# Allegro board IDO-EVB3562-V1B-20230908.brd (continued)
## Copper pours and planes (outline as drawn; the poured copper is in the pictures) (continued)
VCC_3V3 on TOP: 13.57,13.88 12.76,13.88 12.56,13.67 12.56,13.19 12.33,12.96 11.64,12.96 11.58,13.03 11.58,14.1 11.59,14.1 11.82,14.33 11.97,14.33 12.18,14.54 12.18,14.99 14,16.8 14.18,16.8 14.43,16.55 14.43,15.39 13.72,14.68 13.72,14.03
VCC_3V3 on TOP: 27.95,13.93 27.85,14.03 27.85,15.37 28.02,15.55 30.13,15.55 30.28,15.4 30.28,14.31 29.9,13.93
VCC_3V3 on BOTTOM: 7.07,64.04 6.84,64.27 6.84,65.64 7.02,65.82 7.78,65.82 8.13,66.17 8.18,66.17 8.18,66.22 9.99,68.03 26.58,68.03 27.13,68.59 27.13,69.63 27.62,70.11 28.15,70.11 28.16,70.1 28.65,70.1 28.66,70.09 29.55,70.09 30.26,69.37 30.26,66.53 29.22,65.49 9.89,65.49 9.56,65.16 9.56,65.14 8.46,64.04
VCC_3V3 on BOTTOM: outline of 202 points within 6.13,7.27 74.61,39.02
VCC_3V3 on L2-VCC: 78.11,71.94 78.11,70.52 76.94,69.35 72.4,69.35 69.98,66.94 65.41,66.94 63.18,69.17 59.32,69.17 58.25,68.1 58.25,66.07 58.96,65.36 58.96,64.96 58.81,64.8 58.25,64.8 58.1,64.96 30.06,64.96 27.24,67.77 27.24,69.91 27.87,70.54 34.68,70.54 38.36,66.86 53.37,66.86 57.21,70.7 64.24,70.7 66.2,68.74 68.79,68.74 71.33,71.28 76.11,71.28 76.84,72.02 78.04,72.02
VCC_3V3 on L2-VCC: 3.46,63.15 3.46,42.83 5.11,41.18 5.11,35.59 5.49,35.21 8.03,35.21 8.54,35.72 8.54,42.2 8.48,42.26 8.48,52.67 6.26,54.9 6.26,62.39 6.64,62.77 9.05,62.77 9.43,63.15 9.43,66.2 9.11,66.52 6.45,66.52 5.75,65.82 5.75,64.8 5.24,64.29 4.6,64.29
VCC_DCIN on TOP: 10.14,76.46 10.14,74.07 14.33,74.07 14.33,76.28 12.52,78.1 11.78,78.1
VCC_DCIN on L2-VCC: 14.31,75.42 14.31,73.87 13.75,73.31 12.33,73.31 10.85,71.84 10.85,69.81 9.43,68.38 5.87,68.38 4.73,67.24 4.73,64.8 3.08,63.15 3.08,42.58 4.73,40.93 4.73,35.47 5.37,34.83 7.53,34.83 7.78,34.58 7.78,27.59 7.4,27.21 4.94,27.21 4.22,26.5 1.76,26.5 1.23,27.03 1.23,69.12 3.08,70.98 6.69,70.98 8.95,73.24 8.95,76.46 6.76,78.65 1.91,78.65 1.37,79.19 1.37,83.71 2.67,85.02 9.35,85.02 10.32,84.06 10.32,79.41
VCC_DMIC on TOP: 64.88,7.14 63.15,5.42 62.52,5.42 62.42,5.52 62.42,7.93 62.77,8.29 72.42,8.29 72.55,8.16 72.55,7.53 72.17,7.14
VCC_LEDA+ on TOP: 2.93,67.21 5.91,67.21 5.91,67.22 7.12,67.22 7.27,67.06 7.27,66.05 7.25,66.02 4.73,66.02 4.38,66.02 4.1,65.74 4.1,63.58 5.24,62.44 5.24,58.99 4.91,58.66 3.18,58.66 2.57,59.27 2.57,66.86
VCC_LEDA+ on BOTTOM: 4.16,56.93 2.83,56.93 2.57,57.18 2.57,59.21 2.68,59.32 3.37,59.32 3.37,59.34 3.59,59.34 3.72,59.47 3.72,61.75 3.84,61.88 4.6,61.88 5.58,60.9 5.58,58.35
VCC_LEDA+ on BOTTOM: 3.82,66 3.69,66.12 3.69,67.17 3.79,67.27 5.39,67.27 5.52,67.14 5.52,66.1 5.42,66 5.25,66 5.24,66 5.09,66.02 4.95,66 4.94,66
VCC_LEDK- on TOP: 5.72,65.77 5.72,65.76 7.2,65.76 7.27,65.69 7.27,65.03 7.21,64.97 5.72,64.97 5.72,64.96 5.57,64.96 5.19,64.57 4.63,64.57 4.4,64.8 4.4,65.44 4.73,65.77
VCC_LEDK- on BOTTOM: 3.82,64.78 3.82,65.64 3.92,65.74 6.48,65.74 6.56,65.67 6.56,64.85 6.33,64.63 3.97,64.63
VCC_M2 on TOP: 96.76,28.89 96.76,28.05 96.73,28.02 96.29,28.02 96.29,28.03 96.04,28.06 95.8,28.03 95.77,28.02 95.69,27.99 95.65,27.97 95.58,27.94 95.52,27.9 94.39,27.9 94.14,28.15 94.14,30.18 94.44,30.49 94.44,32.09 94.5,32.14 96.3,32.14 96.55,31.88 96.55,29.09
VCC_M2 on TOP: 99.47,42.58 98.97,42.07 98.97,38.33 98.17,37.53 96.27,37.53 96.17,37.62 96.17,38.49 96.4,38.89 96.17,39.3 96.17,39.51 96.4,39.91 96.17,40.32 96.17,40.52 96.4,40.93 96.17,41.33 96.17,43.47 96.04,43.59 96.04,44.74 95.95,44.83 95.77,45.03 95.51,45.1 95.38,45.22 95.38,45.83 95.56,46.01 95.64,46.01 95.84,45.95 96.04,45.94 96.24,45.95 96.44,46 96.45,46.01 96.55,46.01 96.65,46.1 96.77,46.19 96.89,46.29 96.98,46.4 97.06,46.51 99.35,46.51 99.47,46.39 99.47,44.74
VCC_M2 on BOTTOM: 95.68,38.48 96.1,38.45 96.38,38.77 98.02,38.77 98.71,38.07 98.71,34.35 98.69,34.33 98.69,30.43 98.71,30.41 98.71,28.18 98.38,27.85 96.64,27.85 95.95,28.05 95.32,27.72 93.88,27.72 93.25,28.34 93.25,28.61 93.41,28.76 95.32,28.76 95.32,29.03 95.41,29.12 95.41,30.39 95.32,30.39 95.32,30.47 93.42,30.47 93.38,30.51 93.38,30.63 93.38,30.64 93.44,30.87 93.38,31.1 93.38,31.11 93.38,31.31 93.38,31.32 93.44,31.55 93.38,31.79 93.38,32.16 93.48,32.26 95.32,32.26 95.32,32.29 95.41,32.29 95.41,38.26 95.65,38.5
VCC_M2 on BOTTOM: 93.7,44.99 93.62,45.02 93.59,45.1 93.6,45.14 93.6,46.39 95.03,46.39 95.28,46.13 95.39,46.13 95.4,46.13 96.04,45.94 96.69,46.13 96.7,46.13 97.06,46.13 97.29,45.91 97.29,44.71 97.19,44.61 96.17,44.61 95.95,44.83 95.62,45.08 95.22,44.99
VCC_OUT on TOP: 124.37,5.85 124.37,3.06 124.26,2.95 123.12,2.95 123.11,2.96 122.84,2.99 122.57,2.96 122.56,2.95 122.2,2.95 121.78,3.37 121.74,3.37 121.6,3.51 121.6,5.62 121.27,5.95 121.27,7.83 121.34,7.91 122.36,8.19 123.5,8.19 123.78,7.91 124.8,7.91 124.87,7.83 124.87,6.36
VCC_OUT on TOP: 86.27,7.02 90.61,7.02 90.94,6.69 90.94,2.37 90.76,2.19 88.93,2.19 87.28,3.84 81.69,3.84 80.72,2.87 80.72,2.15 80.47,1.91 79.64,1.91 79.29,2.26 79.29,3.25 81.41,5.37 82.71,5.37 83.24,5.9 85.15,5.9
VCC_OUT on BOTTOM: outline of 82 points within 87.05,1.28 124.75,6.76
VCC_RMII on BOTTOM: 40.27,60.9 40.11,60.9 39.64,60.43 39.2,60.43 39.17,60.46 39.17,61.04 39.53,61.4 39.53,64.45 39.76,64.68 41.28,64.68 41.49,64.47 41.49,64.19 41.84,63.84 41.84,61.4 41.7,61.26 40.53,61.26 40.42,61.15 40.42,61.06
VCC_SIM on TOP: 109.25,59.47 109.25,60.28 109.51,60.54 114.76,60.54 115.4,59.9 117.13,59.9 117.43,59.6 117.43,58.81 117.38,58.76 114.89,58.76 114.36,59.29 109.43,59.29
VCC_SIM on BOTTOM: 108.24,58.99 107.95,59.27 107.89,59.35 107.81,59.42 106.69,60.54 106.69,62.31 106.94,62.57 108.24,62.57 108.41,62.39 108.41,60.64 108.74,60.31 110.42,60.31 110.83,59.9 110.83,59.09 110.73,58.99
VCC_SIM on BOTTOM: 115.22,57.46 114.79,57.89 114.79,58.99 114.87,59.06 115.83,59.06 116.14,59.37 117.25,59.37 117.58,59.04 117.58,57.61 117.43,57.46
VCC_SYS on TOP: 26.38,56.09 26.17,56.29 25.58,56.29 25.48,56.19 24.81,56.19 24.81,56.99 24.75,56.99 24.75,57.03 23.65,58.12 23.65,67.47 23.83,67.65 27.85,67.65 28.35,67.14 28.35,65.92 29.12,65.16 30.39,65.16 30.84,64.7 30.84,60.94 30.84,60.94 30.8,60.74 30.84,60.54 30.84,60.53 30.84,58.88 30.23,58.28 30.23,56.32 30.13,56.22 27.08,56.22 26.98,56.12 26.62,56.12 26.6,56.09
VCC_TP on TOP: 10.83,34.7 11.67,35.54 13.02,35.54 13.11,35.45 13.1,35.42 13.09,35.32 13.11,35.22 13.11,35.21 13.11,34.09 13.29,33.92 13.29,33.05 13.23,32.99 12.28,32.99 12.26,33 12.25,33.02 12,33.19 11.7,33.18 11.69,33.18 10.93,33.18 10.83,33.28
VCCA_RMII on BOTTOM: 35.26,59.34 35.16,59.45 35.16,59.49 35.16,60.27 35.11,60.27 35.11,60.48 35.29,60.66 35.29,61.93 35.59,62.24 36.58,62.24 36.81,62.47 38.97,62.47 39.07,62.36 39.07,61.37 38.95,61.25 38.08,61.25 37.23,60.4 35.91,60.4 35.9,60.38 35.75,60.38 35.63,60.27 35.48,60.27 35.48,59.49 35.48,59.45 35.49,59.41 35.42,59.34
VCCIO_WL on TOP: 113.09,28.48 112.94,28.63 112.94,29.09 111.79,30.23 110.27,30.23 110.01,30.49 110.01,31.63 110.17,31.78 112.43,31.78 112.81,31.4 113.6,31.4 113.67,31.33 113.67,28.51 113.65,28.48
VDD10_PHY0 on BOTTOM: 47.63,52.46 47.63,52.79 47.73,52.89 48.37,52.89 48.42,52.84 48.42,50.71 48.29,50.58 47.66,50.58 47.4,50.33 47.4,49.69 47.28,49.56 46.77,49.56 46.57,49.77 46.57,50.1 46.55,50.11 46.55,50.15 45.92,50.78 45.92,51.63 46.13,51.85 47.02,51.85 47.27,52.1 47.28,52.1 47.49,52.22 47.61,52.43 47.61,52.44
VDD10_PHY2 on BOTTOM: 70.76,49.57 70.62,49.72 70.62,50.55 70.47,50.71 70.29,50.71 70.29,50.72 69.46,50.72 69.3,50.88 69.3,51.87 69.4,51.98 72.04,51.98 72.7,51.32 73.34,51.32 73.44,51.21 73.44,49.69 73.32,49.57
VDD_3V8 on TOP: 106.94,54.21 106.94,55.02 106.57,55.39 105.58,55.39 105.44,55.53 105.44,56.04 105.67,56.27 108.39,56.27 108.43,56.31 108.44,56.32 108.44,58.61 108.52,58.68 109.02,58.68 109.1,58.61 109.1,54.62 109.05,54.57 108.19,54.57 107.96,54.34 107.96,54.21 107.78,54.03 107.12,54.03
VDD_3V8 on TOP: 120.4,56.27 120.45,56.32 120.48,58.58 121.7,58.58 122.46,58.58 122.64,58.4 122.64,54.16 122.59,54.11 122.59,53.35 121.92,52.68 120.78,52.68 120.4,53.06
VDD_3V8 on TOP: 101.79,64.45 101.64,64.59 101.64,66.95 101.63,66.95 101.63,68.59 101.75,68.7 103.58,68.7 104.22,69.35 104.93,69.35 105.27,69.02 105.27,67.65 104.6,66.99 103.18,66.99 103.14,66.95 103.12,66.95 103.12,66.93 103.11,66.91 103.11,64.65 102.9,64.45
VDD_3V8 on TOP: 99.07,51.8 98.61,51.34 94.14,51.34 93.89,51.59 93.89,54.26 93.43,54.72 93.43,56.88 93.61,57.06 94.6,57.06 95.05,57.51 95.05,58.99 95.38,59.32 97.72,59.32 97.89,59.15 97.89,58.75 97.9,58.73 97.9,56.32 98.13,56.09 99.22,56.09 99.45,55.86 99.45,54.21 99.07,53.83
VDD_3V8 on BOTTOM: outline of 85 points within 96.55,48.93 123.05,68.08
VDD_5V on TOP: 14.26,49.44 14.29,49.47 14.46,49.82 14.45,50.22 14.38,50.41 14.26,50.58 14.26,51.24 14.31,51.29 15.58,51.29 15.78,51.09 17.3,51.09 17.89,50.51 17.89,50.5 17.98,50.37 18.11,50.28 18.12,50.27 19.79,48.6 19.79,43.82 20.12,43.49 20.12,42.12 19.82,41.82 18.83,41.82 18.45,42.2 18.45,44.51 18.49,44.51 18.49,45.47 18.41,45.55 18.02,45.55 17.85,45.71 17.85,47.8 16.95,48.7 14.99,48.7
VDD_5V on TOP: 83.92,11.78 81.33,11.78 81.19,11.92 81.19,13.11 80.8,13.49 79.53,13.49 79.41,13.62 79.41,14.51 79.79,14.89 81.57,14.89 83.47,12.99 83.98,12.99 84.11,12.86 84.11,11.97
VDD_5V on BOTTOM: outline of 177 points within 0.87,1.27 84.46,51.72 ; 1 cut-out
VDD_LCD on TOP: 9.43,38.01 9.56,38.13 9.56,38.77 9.68,38.89 10.32,38.89 10.45,38.77 11.84,38.77 11.97,38.89 11.97,41.23 12.12,41.38 13.34,41.38 13.65,41.08 13.65,36.79 10.37,36.79 8.77,35.19 8.77,29.4 8.62,29.24 5.85,29.24 5.14,29.95 5.14,37.57 5.57,38.01
VDD_LCD_ on TOP: 10.7,43.85 10.84,43.99 10.84,46.3 11.31,46.77 12.48,46.77 12.86,47.15 12.86,48.37 13.24,48.75 13.98,48.75 15.78,46.95 15.78,42.07 15.53,41.82 11.08,41.82 10.7,42.2
(no net) on TOP: 0.51,87.97 0.95,89.05 2.03,89.49 118.47,89.49 118.65,89.31 118.65,88.55 118.78,88.42 122.97,88.42 123.1,88.55 123.1,89.31 123.27,89.49 132.97,89.49 134.05,89.05 134.49,87.97 134.49,2.03 134.05,0.95 132.97,0.51 2.03,0.51 0.95,0.95 0.51,2.03 ; 117 cut-outs
(no net) on BOTTOM: 2.03,0.51 0.95,0.95 0.51,2.03 0.51,87.97 0.95,89.05 2.03,89.49 13.75,89.49 13.75,77.29 15.32,75.72 17.69,75.72 18.7,76.74 18.7,78.77 16.92,80.55 16.92,86.56 17.13,86.77 31.32,86.77 31.53,86.56 31.53,80.8 29.75,79.03 29.75,76.87 31.02,75.6 36.31,75.6 37.75,77.04 37.75,78.6 35.85,80.51 35.85,85.93 36.69,86.77 50.62,86.77 50.96,86.44 50.96,81.02 49.05,79.11 49.05,76.78 50.24,75.6 56.12,75.6 57.69,77.17 57.69,78.73 55.53,80.89 55.53,86.18 55.87,86.52 70.18,86.52 70.39,86.31 70.39,80.76 68.49,78.86 68.49,76.91 69.67,75.72 72.13,75.72 73.44,77.04 73.44,89.49 118.47,89.49 118.65,89.31 118.65,88.55 118.78,88.42 122.97,88.42 123.1,88.55 123.1,89.31 123.27,89.49 132.97,89.49 134.05,89.05 134.49,87.97 134.49,2.03 134.05,0.95 132.97,0.51 ; 97 cut-outs
HP_SNS on TOP (solid shape): 124.47,87.35 125.53,86.63 123.39,86.12 123.29,86.15 123.25,86.25 123.37,88.03
HPL_OUT+ on TOP (solid shape): 124.48,80.79 125.53,80.08 123.36,79.95 123.27,79.99 123.23,80.08 123.37,81.48
HUB_1V8 on BOTTOM: 119.18,40.29 118.4,40.29 117.63,41.05 117.63,45.75 116.11,47.28 109.51,47.28 109,46.77 109,45.24 107.73,43.97 106.79,43.97 106.48,44.28 106.48,44.69 107.16,45.36 107.16,48.79 107.68,49.31 112.43,49.31 113.32,48.42 116.26,48.42 118.96,45.73 118.96,41.53 118.96,41.51 119.46,41 119.46,40.58
HUB_3V3 on TOP: 117.76,50.58 117.76,49.77 116.21,48.22 116.21,47.38 116.06,47.23 115.6,47.23 115.53,47.3 115.53,47.4 115.53,47.44 115.53,48.81 115.53,48.85 115.53,49.46 116.7,50.63 117.71,50.63
HUB_3V3 on TOP: 111.34,40.42 111.34,38.74 111.54,38.54 111.84,38.54 112.05,38.74 112.05,40.39 112.12,40.47 112.28,40.47 112.35,40.39 112.35,40.29 112.34,40.26 112.34,38.89 112.35,38.85 112.35,38.82 112.35,37.37 112.22,37.24 110.42,37.24 110.4,37.27 110.4,38.13 110.85,38.59 110.93,38.64 110.99,38.72 111.03,38.77 111.03,40.42 111.11,40.5 111.26,40.5
HUB_3V3 on BOTTOM: 105.54,41.97 105.54,43.31 105.06,43.72 105.04,44.52 105.05,44.56 105.06,44.66 105.04,44.76 105.03,45.09 105.87,45.93 105.87,48.19 106.23,48.55 106.71,48.55 106.87,48.39 106.87,45.5 106.23,44.86 106.23,44.18 106.87,43.54 106.89,43.54 110.01,40.42 117.63,40.42 118.02,40.04 119.29,40.04 119.79,40.55 119.79,41.05 119.21,41.64 119.21,45.88 116.67,48.42 116.67,48.45 116.36,48.75 114.03,48.75 112.78,49.99 112.78,50.32 113.27,50.81 113.67,50.81 114.49,49.99 116.7,49.99 120.23,46.46 120.23,44.61 121.37,43.47 121.37,39.74 119.63,38.01 107.81,38.01 106.75,39.06 106.75,40.76
PA_5V on TOP: 86.08,15.21 88.68,15.21 89.24,15.77 89.83,15.77 89.85,15.78 91.75,15.78 91.83,15.86 99.85,15.86 100.13,15.58 100.13,14.61 100.03,14.51 98.71,14.51 98.6,14.4 95.91,14.4 95.91,14.36 92.12,14.36 92.12,14.4 89.81,14.4 89.81,14.37 89.69,14.26 89.69,13.62 89.57,13.49 86.29,13.49 86.28,13.51 85.76,12.99 85.76,11.97 85.63,11.84 84.74,11.84 84.61,11.97 84.61,13.75
PHY0_REG_OUT on BOTTOM: 49.77,50.81 49.69,50.88 49.69,53.53 49.95,53.78 49.98,53.78 49.98,53.82 51.37,55.2 52.56,55.2 52.69,55.08 52.68,54.96 52.68,54.56 52.64,54.52 52,54.52 50.58,53.09 50.58,51.35 50.51,51.28 50.46,51.2 50.41,51.07 50.41,50.92 50.38,50.84 50.31,50.81
PHY2_REG_OUT on BOTTOM: 69.43,53.25 69.32,53.35 69.32,53.73 69.43,53.85 69.49,54 69.49,54.25 69.38,54.47 69.38,54.48 69.36,54.52 69.56,54.73 70.33,54.73 71,55.4 71,56.42 71.34,56.76 71.41,56.75 71.97,56.75 72.08,56.77 72.18,56.83 72.39,56.83 72.39,56.73 72.39,55.52 72.11,55.24 71.83,55.11 71.69,54.83 71.66,54.8 71.66,53.47 71.43,53.25
SIM_CLK on BOTTOM (solid shape): 113.28,60.58 112.72,60.02 112.68,60.01 112.64,60.02 112.08,60.58 112.68,61.51
SIM_DATA on BOTTOM (solid shape): 113.31,83.75 112.72,83.17 112.68,83.15 112.64,83.17 112.06,83.75 112.68,84.68
SIM_RST on BOTTOM (solid shape): 110.85,62.48 110.9,62.46 110.91,62.41 110.84,60.58 110.13,61.49 109.44,62.41
USB_OTG on TOP: 97.06,74.71 95.79,73.44 95.79,70.26 94.52,70.26 94.52,75.22 95.16,75.85 95.16,77.5 95.41,77.76 96.81,77.76 97.06,77.5
USB_OTG on BOTTOM: 94.9,81.06 90.08,81.06 89.82,80.8 89.82,79.92 90.08,79.66 91.6,79.66 92.74,78.52 94.14,78.52 95.16,77.5 95.16,76.74 95.41,76.49 95.66,76.49 96.81,77.63 96.81,79.15
N69227900 on TOP: 29.4,38.77 29.5,38.67 29.5,36.61 27.13,36.61 27.08,36.66 27.08,38.59 27.26,38.77
N69764515 on TOP: 91.09,53.37 90.96,53.5 90.96,56.67 91.22,56.93 91.98,56.93 92.16,56.75 92.16,56.68 92.15,56.68 92.15,54.64 92.16,54.64 92.16,53.53 92.01,53.37
N69774891 on TOP: 110.01,27.59 109.89,27.72 109.89,28.86 110.4,29.37 112.3,29.37 112.55,29.11 112.55,28.48 112.81,28.23 112.81,27.72 112.68,27.59
N69774891 on TOP: 113.93,32.8 113.72,33 113.72,34.45 113.98,34.7 117.38,34.7 117.76,34.32 117.76,32.93 117.63,32.8
N69774891 on BOTTOM: 110.65,28.1 110.14,28.61 110.14,29.37 113,32.23 113.03,32.22 113.53,32.33 113.64,32.83 113.63,32.86 115.09,34.32 116.49,34.32 116.75,34.07 116.75,33.43 114.58,31.27 114.58,31.27 111.41,28.1
N69774914 on TOP: 113.95,28.48 113.93,28.51 113.93,31.45 114,31.53 115.98,31.53 116.06,31.45 116.06,30.84 115.73,30.51 115.44,30.51 115.07,30.57 114.77,30.34 114.59,30.16 114.59,28.53 114.54,28.48
N69811283 on BOTTOM: 2.32,52.74 2.19,52.86 2.19,55.28 2.32,55.4 4.6,55.4 5.06,54.95 5.16,54.81 5.29,54.72 5.62,54.39 5.62,52.99 5.37,52.74
N69841804 on TOP: 18.22,66.43 11.87,66.43 10.57,67.72 10.57,70.64 10.7,70.77 19.02,70.77 22.27,67.52 22.27,62.91 22,62.64 20.1,62.64 19.74,63 19.74,64.9
N69865878 on TOP (solid shape): 124.46,78.59 125.53,77.88 123.38,77.43 123.33,77.45 123.31,77.5 123.37,79.28
N70165141 on TOP: 21.11,47.66 20.86,47.91 20.86,52.48 21.11,52.74 23.02,52.74 23.26,52.98 23.33,53.03 23.44,53.16 24.21,53.16 24.38,53.12 24.56,53.16 24.9,53.16 24.93,53.15 25.66,53.88 25.66,53.88 25.66,54.82 25.66,54.82 25.66,54.92 25.43,55.15 25.43,55.79 25.63,55.98 25.67,55.98 25.67,56.02 25.69,56.04 26.03,56.04 26.03,55.93 26.18,55.93 26.32,55.79 26.32,55.15 26.07,54.9 26.07,54.83 26.06,54.82 26.06,53.86 26.13,53.78 26.53,53.78 26.73,53.58 26.73,52.99 24.54,50.81 24.54,48.04 24.16,47.66
N70208813 on TOP: 90.58,23.4 90.63,23.35 90.63,22.72 89.42,21.5 89.42,17.79 88.42,16.8 82.71,16.8 81.44,18.07 81.44,20.48 81.57,20.61 83.22,20.61 83.73,20.1 87.15,20.1 87.68,20.62 87.68,20.85 87.74,20.91 87.74,22.51 87.76,22.54 87.76,22.99 88.17,23.4
N70210968 on TOP: 103.61,27.29 102.62,27.29 102.42,27.08 102.42,25.81 102.37,25.76 101.66,25.76 101.53,25.89 101.53,27.92 101.66,28.05 103.64,28.05 103.69,28 103.69,27.36

Small or netless copper shapes (teardrops, artwork), in the pictures only: 86 on TOP, 50 on BOTTOM

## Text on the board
Ref Des/Silkscreen Bottom: ON | GND | PWM | DCIN | NC | D3P | CLKP | D2P | D1P | D0P | VCC | 5V0 | 3V3 | VLCD | D3N | D2N | D1N | D0N | CLKN | SPKN | SPKP | SNSP | SNSN | BDIV | R1204 | R1203 | R1205 | R1206 | RECOVERY_KEY | DP3 | DM3 | DP4 | DM4 | CAN_L | CAN_H | VOLN | VOLP | VORN | VORP | RX8 | TX8 | R402 | R401 | C317 | C319 | RX6 | TX6 | ADC5 | RX9 | ADC4 | TX9 | ADC3 | ADC2 | ADC1 | ADC0 | MISO | RX4 | MOSI | TX4 | CLK | CS0 | RESET-KEY
User.Comments: CR_UNNAMED_3 | CR_UNNAMED_4
Ref Des/Silkscreen Top: 29 | 1 | 30 | 2 | R410 | R409 | C346 | C345 | IDO-EVB3562-VIB
DIMENSION: FIGURE | SIZE | 11.811 | 28.0 | 31.496 | 35.0 | 36.0 | 39.0 | 39.37 | 40.0 | 65.0 | 66.929 | 93.0 | 102.362 | 145.669 | 23.622 | 44.016 | 45.0 | 47.201 | 55.0 | 62.992 | 90.551 | 127.949 | 128.0 | 78.74x23.622 | 78.74x31.5 | DRILL CHART: TOP to BOTTOM | ALL UNITS ARE IN MILS | PLATED | NON-PLATED | QTY | 1964 | 36 | 18 | 25 | 30 | 3 | 20 | 12 | 2 | 8 | 1 | 4
